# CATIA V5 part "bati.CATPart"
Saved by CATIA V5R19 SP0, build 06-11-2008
Part number: bati
Publications: "entraxe_bati", "longueur_bati", "largeur_base_bati", "epaisseur_bati"
Bounding box of the stored display mesh (mm): x 0 to 100, y -405.895 to 144.105, z -257.772 to -22.849
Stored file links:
  C:\Users\rcousturie\Desktop\EU_thinkMotion\iao\IAO_MMS_Groupe1\vduret\vduret\vduret\CATIA_disque\bati.CATPart
  C:\Users\rcousturie\Desktop\EU_thinkMotion\iao\IAO_MMS_Groupe1\vduret\vduret\vduret\CATIA_disque\vduret.CATProduct
  C:\Users\rcousturie\Desktop\EU_thinkMotion\iao\IAO_MMS_Groupe1\vduret\vduret\vduret\CATIA_disque\coulisse.CATPart
  C:\Users\rcousturie\Desktop\EU_thinkMotion\iao\IAO_MMS_Groupe1\vduret\vduret\vduret\CATIA_disque\disque.CATPart
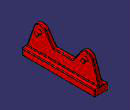
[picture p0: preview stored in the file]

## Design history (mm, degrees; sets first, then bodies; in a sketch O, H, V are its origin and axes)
Parameters
  entraxe_bati = 350 mm
  longueur_bati = 700 mm
  largeur_base_bati = 100 mm
  epaisseur_bati = 30 mm
External parameters (linked from other documents)
  External.diam_int_disque = 30 mm
  External.diam_disque = 200 mm
  External.extrusion_maneton = 30 mm
  External.extrusion_disque = 25 mm
Body1 (main body)
  Sketch1 on yz-plane, origin (0, 0, 0), H (0, 1, 0), V (0, 0, 1)
    line L1 (144.1053, -207.7722) -> (144.1053, -257.7722)
    line L2 (144.1053, -257.7722) -> (-405.8947, -257.7722)
    line L3 (-405.8947, -257.7722) -> (-405.8947, -207.7722)
    arc A1 centre (-305.8947, -72.7722) radius 50 from (-265.0405, -43.9464) to (-353.1093, -56.3169) ccw
    point P5 (-305.8947, -72.7722)
    arc A2 centre (44.1053, -72.7722) radius 50 from (91.32, -56.3169) to (3.2511, -43.9464) ccw
    point P6 (44.1053, -72.7722)
    line L4 (144.1053, -207.7722) -> (91.32, -56.3169)
    line L5 (-405.8947, -207.7722) -> (-353.1093, -56.3169)
    line L6 (-205.8947, -127.7722) -> (-55.8947, -127.7722)
    point P9 (-205.8947, -127.7722)
    line L7 (-205.8947, -127.7722) -> (-265.0405, -43.9464)
    line L8 (-55.8947, -127.7722) -> (3.2511, -43.9464)
    radius A2 = 50 {= External.diam_disque /4}
    radius A1 = 50 {= External.diam_disque /4}
    distance P6 L1 = 100 {= External.diam_disque /2}
    distance P5 L3 = 100 {= External.diam_disque /2}
    distance P6 L2 = 185 {= External.diam_disque /2+85mm}
    distance L2 P5 = 185 {= (External.diam_disque/2)+85mm}
    distance L6 L2 = 130 {= (External.diam_disque /2)+30mm}
    distance P5 P6 = 350 {= entraxe_bati}
    length L6 = 150 {= entraxe_bati -External.diam_disque}
    distance P9 L3 = 200 {= ((entraxe_bati+External.diam_disque )-(entraxe_bati -External.diam_disque ))/2}
    length L1 = 50
    length L3 = 50
    horizontal: L2 H, L6 H
    vertical: L1 V, L3 V
    tangency: L4 A2, L5 A1, A1 L7, L8 A2
  Pad1: profile Sketch1, direction (1, 0, 0), length 100
  Sketch2 on zx-plane, origin (0, 0, 0), H (-1, 0, 0), V (0, 0, 1)
    line L1 (-100, 192.2278) -> (-65, 192.2278)
    line L2 (-65, 192.2278) -> (-65, -207.7722)
    line L3 (-65, -207.7722) -> (-100, -207.7722)
    line L4 (-100, -207.7722) -> (-100, 192.2278)
    point P5 (0, 192.2278)
    line L5 (0, 192.2278) -> (-35, 192.2278)
    line L6 (-35, 192.2278) -> (-35, -207.7722)
    line L7 (-35, -207.7722) -> (0, -207.7722)
    line L8 (0, -207.7722) -> (0, 192.2278)
    point P7 (-35, -207.7722)
    reference projected line E1 (0, -207.7722) -> (-100, -207.7722) from edge [face of Pad1 from Sketch1.L3 | face of Pad1 from Sketch1.L5]
    reference projected line E2 (0, -41.97) -> (0, -180) from edge [start face of Pad1 | face of Pad1 from Sketch1.L5]
    reference projected line E3 (-100, -41.97) -> (-100, -180) from edge [face of Pad1 from Sketch1.L5 | end face of Pad1]
    distance L6 L2 = 30
    distance L1 L3 = 400 {= 2*External.diam_disque}
    length L5 = 35 {= (largeur_base_bati -epaisseur_bati )/2}
    horizontal: L1 H, L3 H, L5 H, L7 H
    vertical: L2 V, L4 V, L6 V, L8 V
    coincidence: P5 L1, P7 L3, L3 E1, L8 E2, L4 E3
  Pocket1: profile Sketch2, direction (0, 1, 0), through (limit type 3), opposite side length 600
  Sketch3 on face of Pocket1 from Sketch2.L2, origin (65, 0, 0), H (0, 1, 0), V (0, 0, 1)
    circle A1 centre (44.1053, -72.7722) radius 15
    point P1 (44.1053, -72.7722)
    reference projected arc E1 centre (44.1053, -72.7722) radius 50 from (90.7413, -54.7422) to (-5.8947, -72.7722) ccw from edge [face of Pocket1 from Sketch2.L2 | face of Pad1 from Sketch1.A2]
    radius A1 = 15 {= External.diam_int_disque /2}
    concentricity: P1 E1
  Pad2: profile Sketch3, direction (1, 0, 0), length 25 {= External.extrusion_disque}
  Sketch4 on face of Pocket1 from Sketch2.L2, origin (65, 0, 0), H (0, 1, 0), V (0, 0, 1)
    circle A1 centre (-305.8947, -72.7722) radius 15
    point P1 (-305.8947, -72.7722)
    reference projected arc E1 centre (-305.8947, -72.7722) radius 50 from (-255.8947, -72.7722) to (-352.5307, -54.7422) ccw from edge [face of Pocket1 from Sketch2.L2 | face of Pad1 from Sketch1.A1]
    radius A1 = 15 {= External.diam_int_disque/2}
    concentricity: P1 E1
  Pad3: profile Sketch4, direction (-1, 0, 0), length 25 {= External.extrusion_disque}, mirrored extent
  Fillet1: radius 5, on face of Pocket1 from Sketch2.L6
  Fillet2: radius 5, on start face of Pad1
  Fillet3: radius 5, on end face of Pad1
  Fillet4: radius 5, on edge [face of Pad1 from Sketch1.L2 | face of Pad1 from Sketch1.L3]
  Fillet5: radius 5, on edge [face of Pad1 from Sketch1.L1 | face of Pad1 from Sketch1.L2]
  Fillet6: radius 5, on edge [face of Pocket1 from Sketch2.L2 | face of Pad1 from Sketch1.L5]; edge [face of Pocket1 from Sketch2.L2 | face of Pad1 from Sketch1.A1]; edge [face of Pad1 from Sketch1.L7 | face of Pocket1 from Sketch2.L2]; edge [face of Pocket1 from Sketch2.L2 | face of Pad1 from Sketch1.L6]; edge [face of Pocket1 from Sketch2.L2 | face of Pad1 from Sketch1.L8]; edge [face of Pocket1 from Sketch2.L2 | face of Pad1 from Sketch1.A2]; edge [face of Pad1 from Sketch1.L4 | face of Pocket1 from Sketch2.L2]; edge [face of Pocket1 from Sketch2.L3 | face of Pocket1 from Sketch2.L2]
  Point1: type Center, Curve edge [face of Pad3 from Sketch4.A1 | face of Pocket1 from Sketch2.L2]
  Line1: type PtDir, RefPoint Point1, Direction start face of Pad3, Start -29, End 29
  Point2: type Center, Curve edge [face of Pocket1 from Sketch2.L2 | face of Pad2 from Sketch3.A1]
  Line2: type PtDir, RefPoint Point2, Direction end face of Pad2, Start -29, End 29
Relations
  Sketch1.radius(A2) = `Paramètres externes\diam_int_disque +20` (deactivated)
  Sketch1.radius(A2) = `Paramètres externes\diam_int_disque` +'20' (deactivated)
  Sketch1.distance(P9 L3) = entraxe_bati /2-`Paramètres externes\diam_disque` /2 (deactivated)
